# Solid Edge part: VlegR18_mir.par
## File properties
Author: Türk
Template: Iso Part.par
Last saved by: Türk
Revision: 2
Application: Solid Edge
Accuracy: 0,990
Username: Türk
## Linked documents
VlegR18.par
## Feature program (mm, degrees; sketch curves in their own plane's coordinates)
part copy "CopiedPart_1"
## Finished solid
Body 1: solid body, 140 faces, 339 edges, 182 vertices, 2 internal voids.
  Faces by surface: cylinder 65, plane 24, torus 23, blend 14, cone 9, spun 5
  Edges by curve: intersection 145, circle 130, line 64
Bounding box of the edges (mm; curved faces can reach further): 235.000 x 457.200 x 457.200, from (-125, -228.6, -228.6) to (110, 228.6, 228.6).
Cylindrical faces by radius (mm): R4 x16, R6 x5, R15 x5, R25 x16, R62.5 x1, R80 x8, R174.2298 x8, R203.6 x2, R216.1 x2, R228.6 x2
Conical faces (half-angle, radius in mm at the cone's reference point): 2.0106 deg R178.4522 x2, 5.4632 deg R201.6202 x2, 54.824 deg R174.2298 x1, 54.824 deg R203.0605 x2, 54.824 deg R203.6 x1, 83.4677 deg R62.5 x1
Toroidal faces (ring radius, tube radius in mm): R79 r1 x7, R136.945 r40 x8, R205.6 r2 x2, R214.1 r2 x2, R226.6 r2 x4
Planar faces by outward normal: +x 4, -x 4, oblique 16
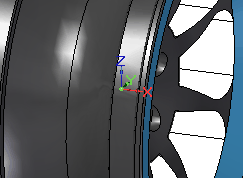
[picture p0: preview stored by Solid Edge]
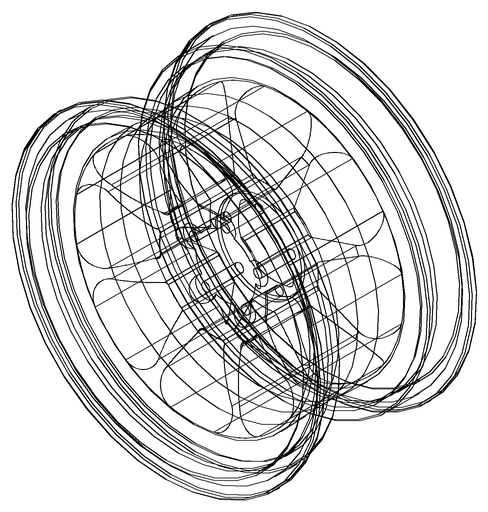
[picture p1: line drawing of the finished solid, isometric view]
